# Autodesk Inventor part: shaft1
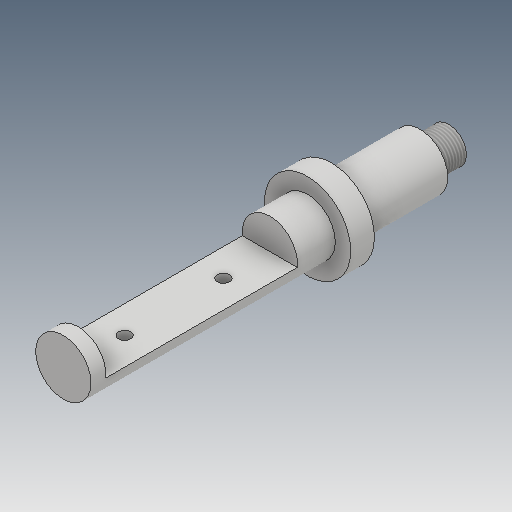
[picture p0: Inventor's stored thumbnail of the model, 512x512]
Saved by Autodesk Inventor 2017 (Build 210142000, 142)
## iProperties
Created: 2016-07
Part Number: shaft1
Material: Generic
Document SubType Name: Modeling
Designer: Sandeep
Density: 1 g/cm^3
Appearance: Default
Author: Sandeep
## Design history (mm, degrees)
sketch "Sketch1"
  geometry: L1 (-125.556, 0)-(92.286, 0); L2 (0, 18)-(28.9, 18); L3 (28.9, 18)-(28.9, 28); L4 (28.9, 28)-(118.7, 28); L5 (118.7, 28)-(118.7, 43.6); L6 (118.7, 43.6)-(142.7, 43.6); L7 (142.7, 43.6)-(142.7, 28); L8 (142.7, 28)-(389.8, 28); L9 (389.8, 28)-(389.8, 0); L10 (0, 18)-(0, 0); L11 (0, 0)-(389.8, 0)
  constraints: 22 end point, 7 perpendicular, 3 point on line, 2 horizontal, 1 collinear
  dimensions: "d0" = 36 diameter of L2 L1; "d1" = 56 diameter of L4 L1; "d2" = 87.2 diameter of L6 L1; "d3" = 28.9 distance between parallel lines of L3 L10; "d5" = 247.1 distance between parallel lines of L9 L7; "d6" = 24 distance between parallel lines of L5 L7; "d7" = 89.8 distance between parallel lines of L3 L5
revolve "Revolution1" sketch "Sketch1" stored, may be unused: angle "d8" = 90 deg
sketch "Sketch5"
  geometry: L1 (-142.7, 28)-(-389.8, 28) reference; L2 (-180.9, 28)-(-374.7, 28); L3 (-374.7, 28)-(-374.7, -3.1); L4 (-374.7, -3.1)-(-180.9, -3.1); L5 (-180.9, -3.1)-(-180.9, 28); L6 (-389.8, 28)-(-389.8, -28) reference; 1 further point
  constraints: 8 end point, 2 parallel, 1 horizontal, 1 perpendicular, 1 point on line
  dimensions: "d18" = 15.1 distance between parallel lines of L6 L3; "d19" = 193.8 distance between parallel lines of L5 L3; "d20" = 24.9 distance from line of L6.end L4
extrude "Extrusion3" cut sketch "Sketch5" stored distance "d21" = 62.5; taper "d22" = 0 deg
sketch "Sketch6"
  geometry: L1 (0, 0.172)-(0, -55.828) reference; L2 (208.9, -55.828)-(208.9, 0.172) reference; L3 (208.9, -27.828)-(-12.149, -27.828); C1 r 6.25 at (146.9, -27.828); C2 r 6.25 at (46.9, -27.828); 3 further points
  constraints: 2 centre point, 2 end point, 2 point on line, 1 equal radius, 1 horizontal, 1 midpoint
  dimensions: "d23" = 100 distance of C1.centre C2.centre; "d24" = 12.5 diameter of C2; "d25" = 46.9 distance from line of L1 C2.centre
extrude "Extrusion4" cut sketch "Sketch6" distance "d26" = 62.5; taper "d27" = 0 deg
thread "Thread1" dims "d28" = 10, "d29" = 0
sketch "Sketch9"
  geometry: L1 (-8, -26.833)-(-8, -22); L2 (-8, -22)-(8, -22); L3 (8, -22)-(8, -26.833); L4 (0, 0)-(0, -22.852); A1 r 28 centre (0, 0) between (8, -26.833) and (-8, -26.833) reference; 2 further points
  constraints: 8 end point, 3 point on circle, 1 parallel, 1 vertical, 1 other
  dimensions: "d34" = 16 distance between parallel lines of L1 L3; "d35" = 50 dimension on A1 L2
extrude "Extrusion5" cut sketch "Sketch9" distance "d36" = 66; taper "d37" = 0 deg
body "Solid1"
